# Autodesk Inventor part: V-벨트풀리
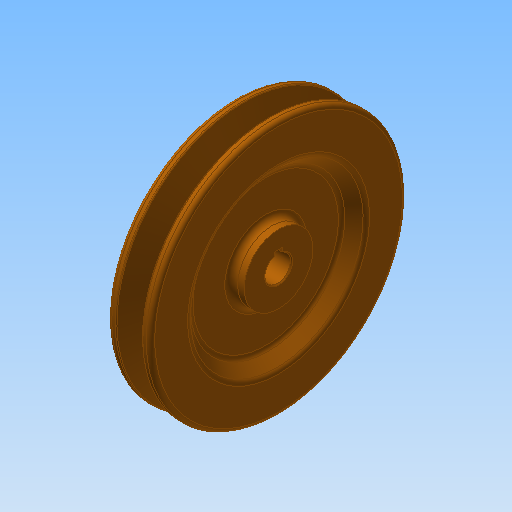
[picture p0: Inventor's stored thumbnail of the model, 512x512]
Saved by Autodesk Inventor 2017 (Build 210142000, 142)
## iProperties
Created: 2015-12
Part Number: V-벨트풀리
Document SubType Name: Modeling
Designer: mdu
Density: 8.08 g/cm^3
Material: 스테인리스강
Appearance: 주황색
Author: mdu
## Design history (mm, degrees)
sketch "스케치1"
  geometry: L1 (-10, 0)-(10, 0); L2 (-10, 0)-(-10, 16); L3 (-10, 16)-(-4, 16); L4 (-4, 16)-(-4, 35); L5 (-4, 35)-(-10, 41); L6 (-10, 41)-(-10, 59.5); L7 (-10, 59.5)-(-6.062, 59.5); L8 (-6.062, 59.5)-(-2.001, 47); L9 (-2.001, 47)-(2.001, 47); L10 (2.001, 47)-(6.062, 59.5); L11 (6.062, 59.5)-(10, 59.5); L12 (10, 59.5)-(10, 41); L13 (10, 41)-(4, 35); L14 (4, 35)-(4, 16); L15 (4, 16)-(10, 16); L16 (10, 16)-(10, 0); L17 (-4.6, 55)-(4.6, 55); 2 further points
  constraints: 34 end point, 7 parallel, 6 equal length, 5 collinear, 3 perpendicular, 2 point on line, 1 coincident, 1 horizontal, 1 midpoint
  dimensions: "d0" = 20 distance of L1.start L1.end; "d1" = 9.2 distance of L17.start L17.end; "d2" = 36 deg angle of L10 L8; "d3" = 4.5 distance between parallel lines of L7 L17; "d4" = 8 distance between parallel lines of L9 L17; "d6" = 110 diameter of L17 L1; "d7" = 32 diameter of L3 L1; "d8" = 82 diameter of L5.end L1; "d9" = 6 distance of L2.end L3.end; "d10" = 135 deg angle of L4 L5
revolve "회전1" sketch "스케치1" stored, may be unused: angle "d11" = 90 deg
fillet "모깎기1" dims "d12" = 2, "d13" = 0.5, "d14" = 1, "d15" = 3
sketch "스케치2"
  geometry: L1 (-2, 5.657)-(-2, 7.8); L2 (-2, 7.8)-(2, 7.8); L3 (2, 7.8)-(2, 5.657); A1 r 6 centre (0, 0) between (-2, 5.657) and (2, 5.657); 1 further point
  constraints: 6 end point, 2 parallel, 2 point on circle, 1 centre point, 1 coincident, 1 perpendicular, 1 vertical
  dimensions: "d16" = 12 diameter of A1; "d17" = 4 distance of L1.end L2.end; "d18" = 13.8 dimension on A1 L2 (computed from d16)
extrude "돌출1" cut sketch "스케치2" stored distance "d19" = 10; taper "d20" = 0 deg
chamfer "모따기2" distance "d24" = 0.5; stored, may be unused: second distance "d25" = 2, angle "d26" = 45 deg
sketch "스케치3" dims "d27" = 100
  geometry: C1 r 2.5 at (0, 50); 2 further points
  constraints: 2 vertical alignment, 1 centre point, 1 coincident, 2 other
  dimensions: "d28" = 5 diameter of C1
extrude "돌출2" join sketch "스케치3" distance "d29" = 1; taper "d30" = 0 deg
node "솔리드1"
